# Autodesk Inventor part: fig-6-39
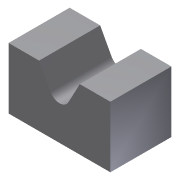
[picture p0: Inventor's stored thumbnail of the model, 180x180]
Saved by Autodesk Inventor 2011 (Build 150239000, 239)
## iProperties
Created: 2005-12
Part Number: fig-6-39
Document SubType Name: Modeling
Designer: CADCIM
Density: 1 g/cm^3
Author: CADCIM
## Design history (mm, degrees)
sketch "Sketch1"
  geometry: L1 (10, 15)-(25, 15); L2 (25, 15)-(25, -15); L3 (25, -15)-(-25, -15); L4 (-25, -15)-(-25, 15); L5 (-25, 15)-(-10, 15); L6 (-10, 15)-(-2, 0); L7 (-2, 0)-(2, 0); L8 (2, 0)-(10, 15); 1 further point
  constraints: 16 end point, 3 equal length, 3 parallel, 1 collinear, 1 horizontal, 1 perpendicular, 1 other
  dimensions: "d0" = 50 distance of L2.end L3.end; "d1" = 25 distance from line of point (0, 0) L2; "d2" = 30 distance of L1.end L2.end; "d3" = 15 distance of L1.start L1.end; "d4" = 15 distance between parallel lines of L1 L7; "d5" = 4 distance of L6.end L7.end; "d6" = 15 distance from line of point (0, 0) L3
extrude "Extrusion1" new body sketch "Sketch1" stored distance "d7" = 30; taper "d8" = 0 deg
fillet "Fillet4" dims "d11" = 5
body "Solid1"
